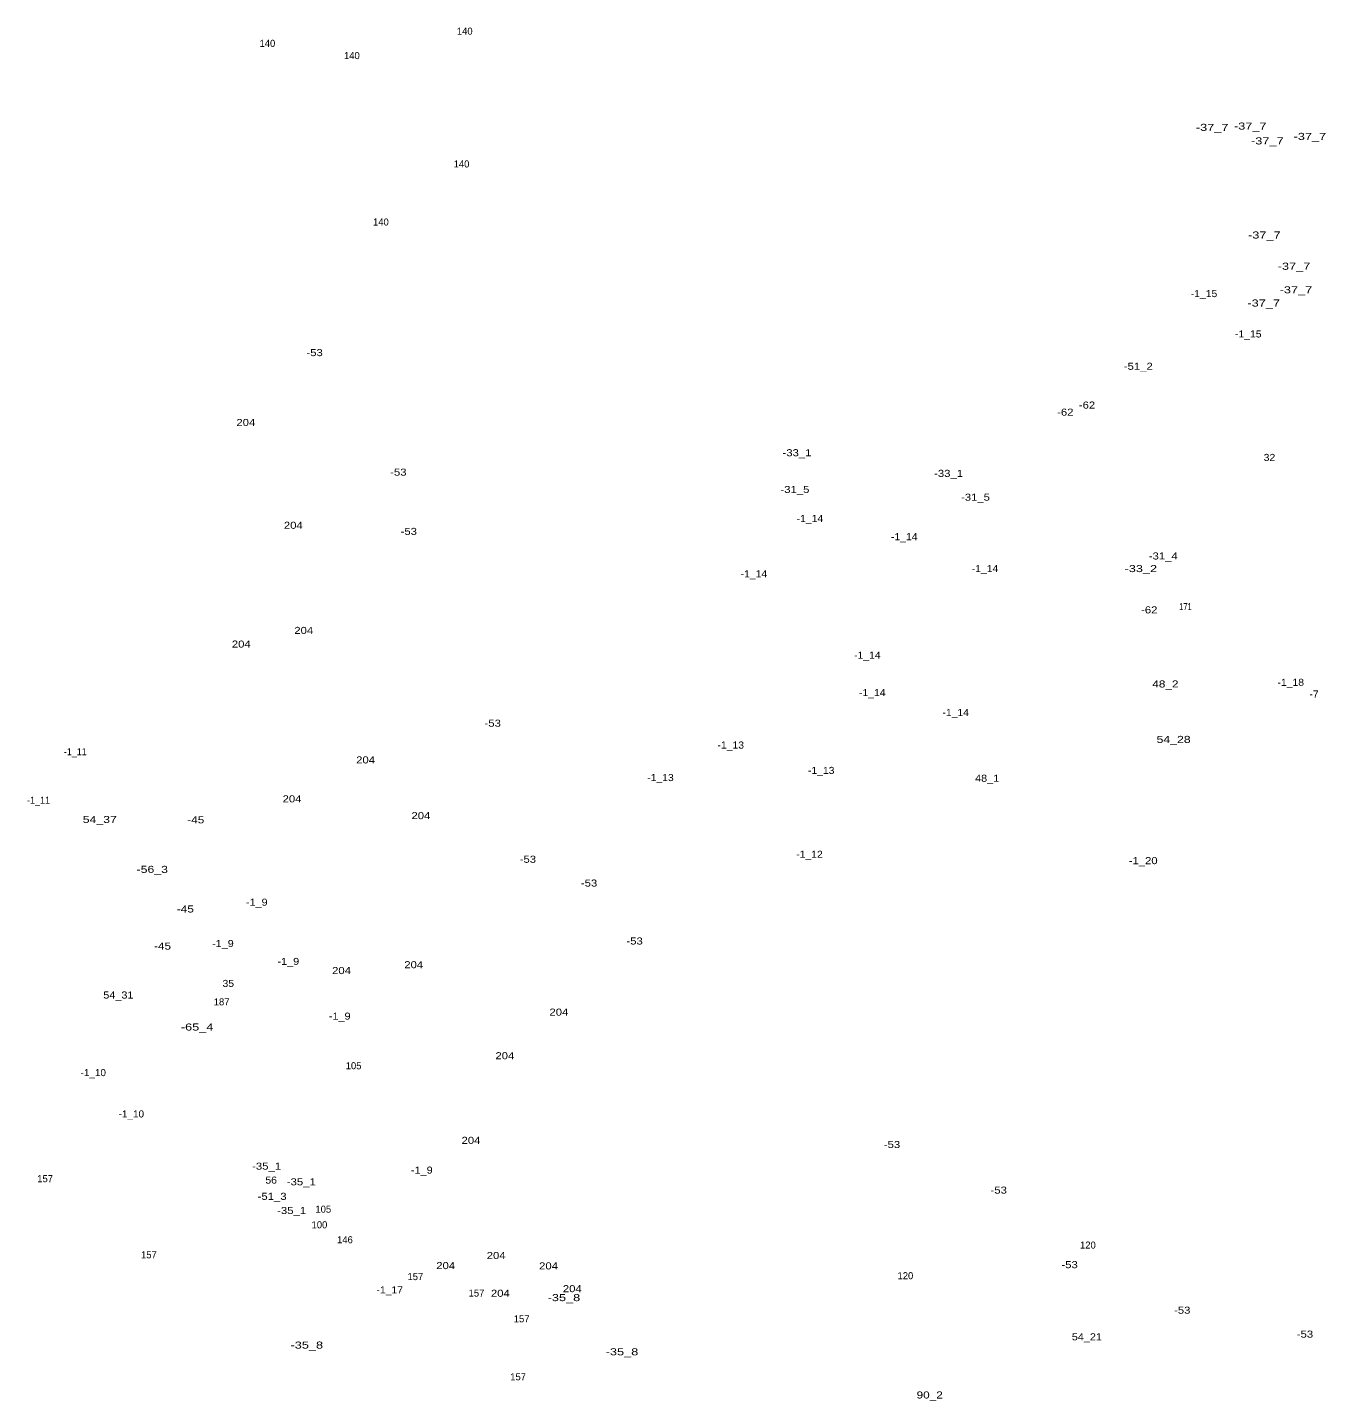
# Model space of a CAD drawing. Extents: x -660405 to -657848, y -988475 to -986360.
# Drawn here: x -660405 to -659669, y -987269 to -986491 of the extents above; entities that cross this region are included whole.
import ezdxf
from ezdxf.enums import TextEntityAlignment as Align

# ---------------------------------------------------------------- set-up
doc = ezdxf.new("R2010")
doc.units = 0
doc.header["$LTSCALE"] = 1.6
doc.layers.add('24', color=7, linetype='Continuous')

msp = doc.modelspace()

# ---------------------------------------------------------------- texts
at = {"layer": '24'}
for s, p in [('140', (-660156.86, -986494.85)), ('140', (-660268.74, -986501.8)), ('140', (-660220.84, -986508.75)), ('140', (-660158.689, -986570.19)), ('140', (-660204.39, -986603.1)), ('187', (-660294.701, -987045.31)), ('105', (-660219.87, -987081.51)), ('157', (-660394.78, -987145.55)), ('105', (-660237.06, -987162.85)), ('100', (-660239.23, -987171.7)), ('146', (-660224.78, -987180.18)), ('157', (-660335.921, -987188.7)), ('120', (-659803.57, -987183.21)), ('157', (-660184.851, -987201.08)), ('120', (-659907.03, -987200.58)), ('157', (-660150.201, -987210.41)), ('157', (-660124.611, -987225.03)), ('157', (-660126.62, -987257.88))]:
    msp.add_text(s, height=4, dxfattribs=at).set_placement(p, align=Align.CENTER)
for s, width, p in [('-37_7', 1.35, (-659733.091, -986549.44)), ('-37_7', 1.35, (-659711.52, -986548.71)), ('-37_7', 1.35, (-659701.841, -986557.12)), ('-37_7', 1.35, (-659677.711, -986554.56)), ('-37_7', 1.35, (-659703.541, -986610.47)), ('-37_7', 1.35, (-659686.721, -986628.19)), ('-1_15', 1.1, (-659737.73, -986643.69)), ('-37_7', 1.35, (-659685.62, -986641.54)), ('-37_7', 1.35, (-659703.9, -986649.04)), ('-1_15', 1.1, (-659712.64, -986666.57)), ('-53', 1.2, (-660241.98, -986677.16)), ('-51_2', 1.2, (-659775, -986684.9)), ('-62', 1.2, (-659804.07, -986706.9)), ('-62', 1.2, (-659816.38, -986710.92)), ('204', 1.2, (-660280.97, -986716.77)), ('-33_1', 1.2, (-659968.48, -986733.93)), ('32', 1.1, (-659700.63, -986736.59)), ('-53', 1.2, (-660194.49, -986744.95)), ('-33_1', 1.2, (-659882.559, -986745.63)), ('-31_5', 1.2, (-659969.669, -986754.75)), ('-31_5', 1.2, (-659867.299, -986759.14)), ('204', 1.2, (-660254.04, -986775.07)), ('-1_14', 1.1, (-659961.16, -986771.19)), ('-53', 1.2, (-660188.59, -986778.54)), ('-1_14', 1.1, (-659907.66, -986781.52)), ('-31_4', 1.2, (-659760.85, -986792.47)), ('-1_14', 1.1, (-659861.91, -986799.61)), ('-33_2', 1.35, (-659773.569, -986799.62)), ('-1_14', 1.1, (-659992.89, -986802.56)), ('-62', 1.2, (-659768.79, -986823.04)), ('171', 0.8, (-659748.231, -986821.18)), ('204', 1.2, (-660248.13, -986834.67)), ('204', 1.2, (-660283.549, -986842.42)), ('-1_14', 1.1, (-659928.6, -986848.72)), ('-1_14', 1.1, (-659925.829, -986869.95)), ('48_2', 1.25, (-659759.63, -986865.04)), ('-1_18', 1.1, (-659688.549, -986864.12)), ('-7', 1.1, (-659675.361, -986870.75)), ('-1_14', 1.1, (-659878.51, -986881.18)), ('-53', 1.2, (-660140.99, -986887.3)), ('-1_13', 1.1, (-660006.049, -986899.67)), ('54_28', 1.3, (-659754.971, -986896.49)), ('-1_11', 0.95, (-660377.65, -986903.47)), ('204', 1.2, (-660213.079, -986908.12)), ('-1_13', 1.1, (-659954.77, -986914.06)), ('-1_13', 1.1, (-660045.9, -986918.12)), ('48_1', 1.15, (-659860.679, -986918.51)), ('-1_11', 0.95, (-660398.5, -986930.97)), ('204', 1.2, (-660254.77, -986930.19)), ('204', 1.2, (-660181.72, -986939.71)), ('54_37', 1.3, (-660363.77, -986941.88)), ('-45', 1.25, (-660309.37, -986942.09)), ('-53', 1.2, (-660121.07, -986964.44)), ('-1_12', 1.1, (-659961.41, -986961.62)), ('-56_3', 1.3, (-660334.02, -986970.17)), ('-1_20', 1.2, (-659772.24, -986965.23)), ('-53', 1.2, (-660086.38, -986977.94)), ('-45', 1.25, (-660315.27, -986992.64)), ('-1_9', 1.15, (-660274.78, -986988.78)), ('-53', 1.2, (-660060.56, -987010.79)), ('-45', 1.25, (-660328.19, -987013.67)), ('-1_9', 1.15, (-660293.971, -987012.21)), ('-1_9', 1.15, (-660256.88, -987022.36)), ('204', 1.2, (-660185.78, -987024.23)), ('204', 1.2, (-660226.73, -987027.55)), ('54_31', 1.15, (-660353.23, -987041.42)), ('35', 1.1, (-660290.929, -987034.84)), ('-1_9', 1.15, (-660227.74, -987053.37)), ('204', 1.2, (-660103.49, -987051.12)), ('-65_4', 1.35, (-660308.58, -987059.57)), ('204', 1.2, (-660134.12, -987075.85)), ('-1_10', 1.05, (-660367.45, -987085.42)), ('-1_10', 1.05, (-660345.86, -987108.85)), ('204', 1.2, (-660153.309, -987123.83)), ('-53', 1.2, (-659914.63, -987126.21)), ('-35_1', 1.2, (-660269.209, -987138.45)), ('-1_9', 1.15, (-660181.191, -987140.69)), ('56', 1.1, (-660266.61, -987146.36)), ('-35_1', 1.2, (-660249.54, -987147.34)), ('-51_3', 1.2, (-660266.079, -987155.57)), ('-53', 1.2, (-659854.11, -987152.05)), ('-35_1', 1.2, (-660255.02, -987163.62)), ('204', 1.2, (-660139.059, -987189.12)), ('204', 1.2, (-660167.66, -987194.84)), ('204', 1.2, (-660109.36, -987195.03)), ('-53', 1.2, (-659813.93, -987194.32)), ('-1_17', 1.1, (-660199.39, -987208.62)), ('204', 1.2, (-660136.669, -987210.53)), ('-35_8', 1.35, (-660100.63, -987213)), ('204', 1.2, (-660095.89, -987207.94)), ('-53', 1.2, (-659750.09, -987220.15)), ('54_21', 1.15, (-659804.15, -987235.21)), ('-53', 1.2, (-659680.51, -987233.7)), ('-35_8', 1.35, (-660246.41, -987239.92)), ('-35_8', 1.35, (-660067.72, -987243.72)), ('90_2', 1.25, (-659893.25, -987268.21))]:
    msp.add_text(s, height=4, dxfattribs=dict(at, width=width)).set_placement(p, align=Align.CENTER)

doc.saveas('drawing.dxf')
